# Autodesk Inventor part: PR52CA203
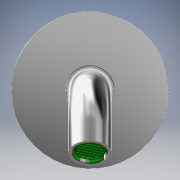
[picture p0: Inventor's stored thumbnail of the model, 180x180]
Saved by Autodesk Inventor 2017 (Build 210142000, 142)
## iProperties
Created: 2021-04
Part Number: PR52CA203
Material: Generico
Document SubType Name: Modeling
Designer: PIZZERA
Density: 1 g/cm^3
Appearance: Default
Author: PIZZERA
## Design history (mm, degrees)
feature "Base3"
node "Solido1"
node "Solido4"
